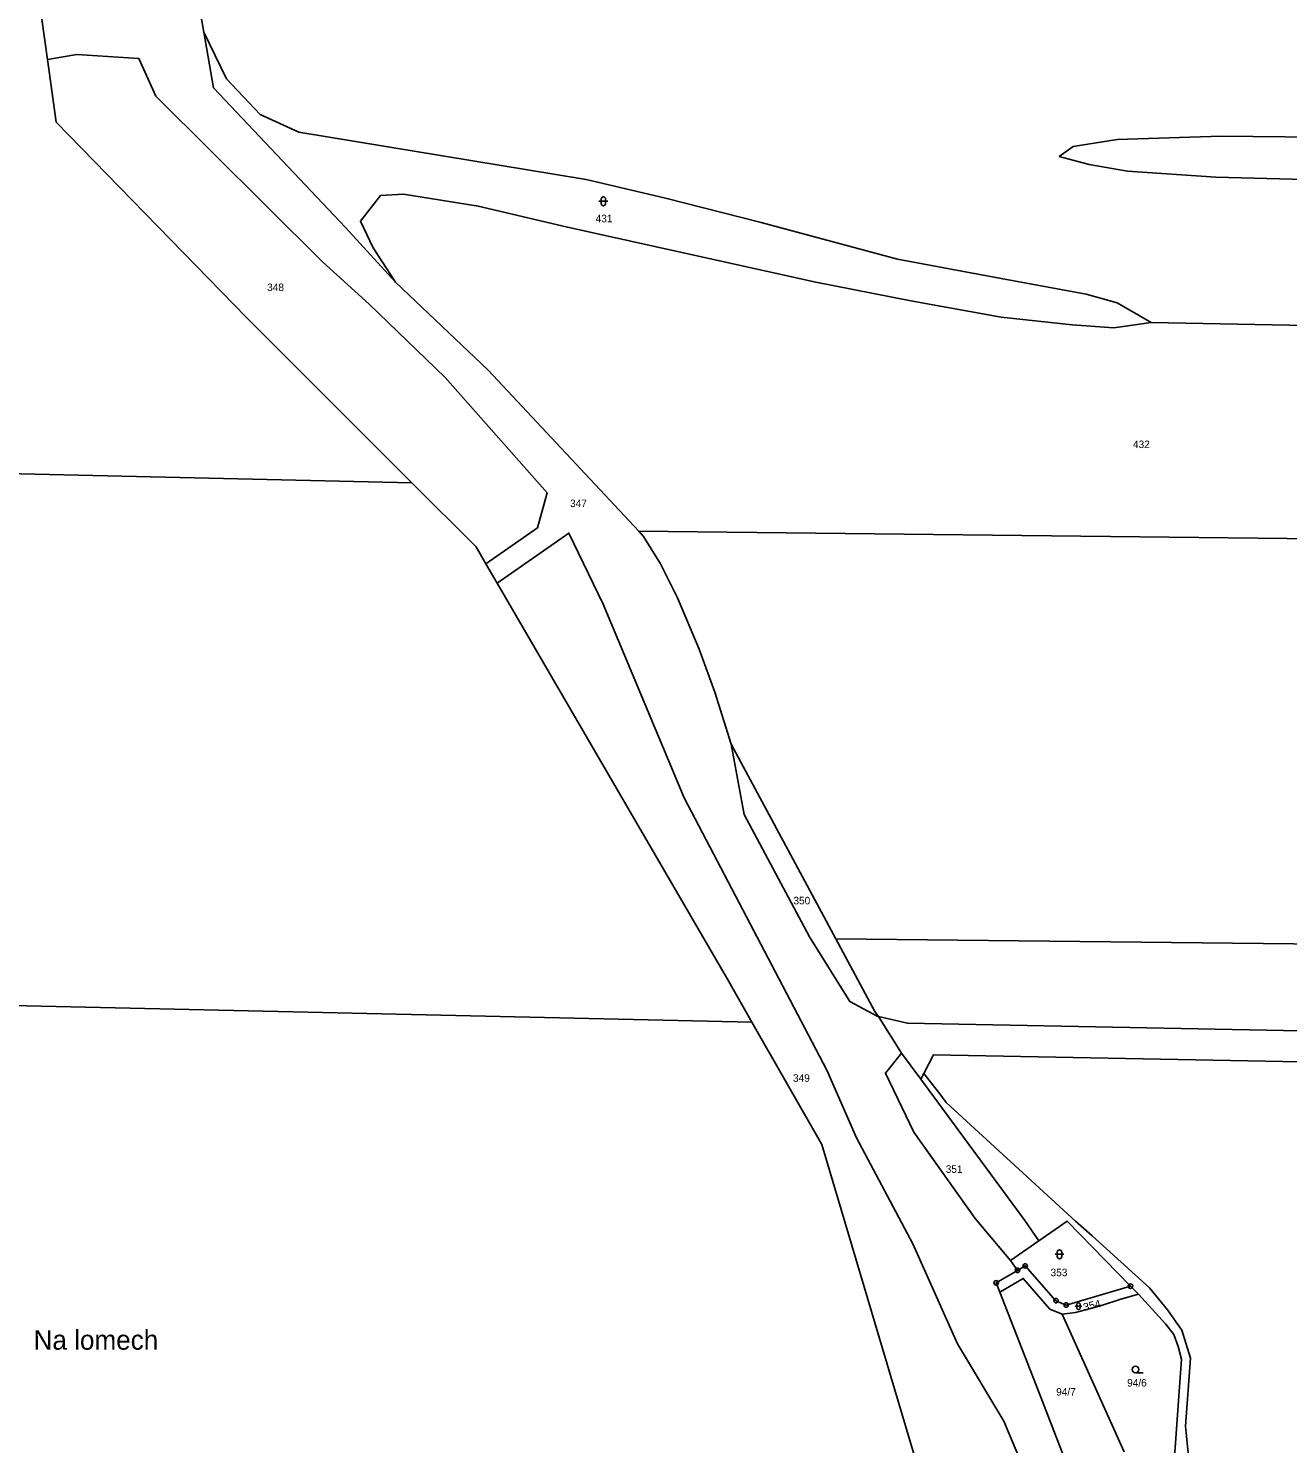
# Model space of a CAD drawing. Extents: x -769392 to -767038, y -1018329 to -1015269.
# Drawn here: x -768810.3 to -768526.3, y -1016085.5 to -1015766.2 of the extents above; entities that cross this region are included whole.
import ezdxf
from ezdxf.enums import TextEntityAlignment as Align

# ---------------------------------------------------------------- set-up
doc = ezdxf.new("R2010")
doc.units = 0
doc.header["$LTSCALE"] = 0.68
for name, color, linetype, lineweight in [('1', 7, 'Continuous', 25), ('3', 7, 'Continuous', 25), ('7', 7, 'Continuous', 13), ('8', 7, 'Continuous', 25)]:
    doc.layers.add(name, color=color, linetype=linetype, lineweight=lineweight)
doc.layers.add('2', color=7, linetype='Continuous')

msp = doc.modelspace()

# ---------------------------------------------------------------- linework, layer by layer
at = {"layer": '1'}
for p, q in [((-768770.74, -1015767.1), (-768772.34, -1015758.02)), ((-768806, -1015773.27), (-768807.26, -1015764.14)), ((-768707.1, -1015887.02), (-768704.55, -1015891.41)), ((-768628.22, -1015971.61), (-768651.76, -1015927.74)), ((-768647.11, -1015990.45), (-768839.41, -1015986.06)), ((-768613.34, -1015997.43), (-768618.56, -1015989.11)), ((-768613.34, -1015997.43), (-768609.02, -1016003.29)), ((-768609.02, -1016003.29), (-768608.35, -1016002)), ((-768582.41, -1016039.73), (-768588.81, -1016044.17)), ((-768587.21, -1016046.41), (-768588.81, -1016044.17)), ((-768561.73, -1016049.98), (-768559.94, -1016051.82)), ((-768563.14, -1016087.38), (-768577.15, -1016056.29))]:
    msp.add_line(p, q, dxfattribs=at)
for points in [[(-768557.04, -1015832.59), (-768564.72, -1015828.14), (-768571.74, -1015826.21), (-768590.86, -1015822.63), (-768614.27, -1015818.31), (-768645.03, -1015810.06), (-768666.63, -1015804.5), (-768684.47, -1015800.34), (-768749.33, -1015789.66), (-768758.05, -1015785.64), (-768765.64, -1015777.58), (-768770.74, -1015767.1)], [(-768770.74, -1015767.1), (-768768.54, -1015779.67), (-768738.76, -1015811.18), (-768727.48, -1015823.46)], [(-768707.1, -1015887.02), (-768695.45, -1015878.88), (-768693.27, -1015871), (-768716.28, -1015845), (-768733.46, -1015828.45), (-768743.96, -1015818.91), (-768781.53, -1015781.56), (-768785.37, -1015773.04), (-768799.39, -1015772.11), (-768806, -1015773.27)], [(-768806, -1015773.27), (-768804.05, -1015787.36), (-768761.11, -1015831.46), (-768723.8, -1015868.72)], [(-768727.48, -1015823.46), (-768732.57, -1015815.73), (-768735.41, -1015809.71), (-768730.9, -1015803.95), (-768725.67, -1015803.63), (-768708.82, -1015806.32), (-768688.73, -1015811.09), (-768632.66, -1015823.46), (-768611.29, -1015827.67), (-768590.89, -1015831.39), (-768574.88, -1015833.14), (-768565.46, -1015833.76), (-768557.04, -1015832.59)], [(-768672.64, -1015879.68), (-768706.61, -1015843.33), (-768727.48, -1015823.46)], [(-768393.76, -1015882.77), (-768393.24, -1015835.72), (-768557.04, -1015832.59)], [(-769059, -1015861.06), (-768887.32, -1015864.98), (-768723.8, -1015868.72)], [(-768723.8, -1015868.72), (-768709.33, -1015883.18), (-768707.1, -1015887.02)], [(-768393.76, -1015882.77), (-768526.38, -1015881.3), (-768672.64, -1015879.68)], [(-768651.76, -1015927.74), (-768655.45, -1015915.94), (-768659.03, -1015906.25), (-768663.92, -1015894.68), (-768667.76, -1015887.04), (-768671.56, -1015880.83), (-768672.64, -1015879.68)], [(-768577.92, -1016113.27), (-768585.77, -1016091.21), (-768590.28, -1016080.47), (-768600.78, -1016062.99), (-768610.85, -1016040.44), (-768623.52, -1016016.53), (-768630.25, -1016001.25), (-768662.38, -1015939.85), (-768680.7, -1015896.15), (-768688.37, -1015880.1), (-768704.55, -1015891.41)], [(-768704.55, -1015891.41), (-768652.35, -1015981.28), (-768647.11, -1015990.45)], [(-768618.56, -1015989.11), (-768618.84, -1015989.05), (-768625.01, -1015985.77), (-768634.09, -1015971.15), (-768648.87, -1015943.58), (-768651.76, -1015927.74)], [(-768618.56, -1015989.11), (-768619.4, -1015988.03), (-768628.22, -1015971.61)], [(-768628.22, -1015971.61), (-768504.28, -1015972.97), (-768394.77, -1015974.17)], [(-768647.11, -1015990.45), (-768631.35, -1016018.03), (-768596.9, -1016133.83)], [(-768395, -1015994.87), (-768504.06, -1015992.76), (-768612.03, -1015990.68), (-768618.56, -1015989.11)], [(-768588.81, -1016044.17), (-768596.74, -1016034.72), (-768610.57, -1016015.23), (-768616.99, -1016001.93), (-768613.34, -1015997.43)], [(-768608.35, -1016002), (-768606.17, -1015997.79), (-768503.74, -1015999.77), (-768400.14, -1016001.77), (-768395, -1015994.87)], [(-768582.41, -1016039.73), (-768585.54, -1016035.19), (-768609.02, -1016003.29)], [(-768531.03, -1016134.27), (-768536.67, -1016125.7), (-768546.18, -1016104.49), (-768548.19, -1016092.82), (-768549.32, -1016081.54), (-768548.21, -1016066.2), (-768550.18, -1016059.91), (-768553.38, -1016055.35), (-768557.44, -1016050.38), (-768570.36, -1016038.63), (-768574.11, -1016035.31), (-768603.29, -1016008.55), (-768604.7, -1016006.61), (-768608.35, -1016002)], [(-768582.41, -1016039.73), (-768576.01, -1016035.29), (-768561.73, -1016049.98)], [(-768587.21, -1016046.41), (-768585.49, -1016045.41), (-768578.53, -1016053.25), (-768576.22, -1016054.23), (-768561.73, -1016049.98)], [(-768587.21, -1016046.41), (-768592.03, -1016049.22), (-768591.21, -1016051.31)], [(-768577.15, -1016056.29), (-768579.88, -1016055.16), (-768585.91, -1016048.23), (-768591.21, -1016051.31)], [(-768575.9, -1016090.56), (-768582.47, -1016073.67), (-768591.21, -1016051.31)], [(-768568.47, -1016054.44), (-768563.87, -1016052.9), (-768559.94, -1016051.82)], [(-768559.94, -1016051.82), (-768553.83, -1016058.45), (-768551.98, -1016060.85), (-768550.95, -1016063.59), (-768550.23, -1016066.43), (-768551.76, -1016087.46), (-768550.46, -1016107.42), (-768550.51, -1016108.5)], [(-768568.47, -1016054.44), (-768574.14, -1016055.95), (-768577.15, -1016056.29)]]:
    msp.add_lwpolyline(points, dxfattribs=at)
msp.add_lwpolyline([(-768562.42, -1015798.46), (-768542.47, -1015799.78), (-768505.13, -1015800.77), (-768469.57, -1015803.07), (-768439.12, -1015804.99), (-768420.78, -1015807.18), (-768395.06, -1015808.66), (-768391.9, -1015808.02), (-768394.8, -1015806.1), (-768405.31, -1015801.53), (-768414.59, -1015798.93), (-768432.56, -1015794.35), (-768442.59, -1015793.04), (-768450.35, -1015792.69), (-768505.18, -1015790.92), (-768541.24, -1015790.54), (-768564.76, -1015791.31), (-768574.64, -1015792.9), (-768577.78, -1015795.16), (-768571.04, -1015796.95)], close=True, dxfattribs=at)
at = {"layer": '3'}
for p, q in [((-768681.611, -1015805.231), (-768679.609, -1015805.231)), ((-768681.111, -1015804.731), (-768681.111, -1015805.732)), ((-768680.109, -1015805.732), (-768680.109, -1015804.731)), ((-768578.231, -1016042.281), (-768578.231, -1016043.282)), ((-768577.229, -1016043.282), (-768577.229, -1016042.281)), ((-768578.731, -1016042.781), (-768576.729, -1016042.781)), ((-768574.231, -1016054.481), (-768572.669, -1016054.481)), ((-768573.84, -1016054.09), (-768573.84, -1016054.871)), ((-768573.06, -1016054.871), (-768573.06, -1016054.09)), ((-768560.583, -1016069.53), (-768558.833, -1016069.53))]:
    msp.add_line(p, q, dxfattribs=at)
msp.add_circle((-768560.5829, -1016068.7798), 0.75, dxfattribs=at)
for centre, radius, start, end in [((-768680.61, -1015804.7309), 0.5, 0, 180), ((-768680.61, -1015805.7309), 0.5, 180, 359.98789), ((-768577.73, -1016042.2809), 0.5, 0, 180), ((-768577.73, -1016043.2809), 0.5, 180, 359.98789), ((-768573.45, -1016054.0907), 0.39, 0, 180), ((-768573.45, -1016054.8707), 0.39, 180, 359.98789)]:
    msp.add_arc(centre, radius, start, end, dxfattribs=at)
at = {"layer": '8'}
for centre, radius in [((-768587.21, -1016046.4099), 0.5), ((-768585.49, -1016045.4099), 0.5), ((-768585.49, -1016045.4099), 0.0303), ((-768592.03, -1016049.2199), 0.5), ((-768587.21, -1016046.4099), 0.0303), ((-768592.03, -1016049.2199), 0.0303), ((-768561.73, -1016049.9799), 0.5), ((-768561.73, -1016049.9799), 0.0303), ((-768578.53, -1016053.2499), 0.5), ((-768578.53, -1016053.2499), 0.0303), ((-768576.22, -1016054.2299), 0.5), ((-768576.22, -1016054.2299), 0.0303)]:
    msp.add_circle(centre, radius, dxfattribs=at)

# ---------------------------------------------------------------- texts
at = {"layer": '2'}
for s, p in [('431', (-768682.36, -1015809.975)), ('348', (-768756.45, -1015825.495)), ('432', (-768561.16, -1015860.915)), ('347', (-768688.13, -1015874.235)), ('350', (-768637.75, -1015963.845)), ('349', (-768637.85, -1016003.875)), ('351', (-768603.4, -1016024.415)), ('353', (-768579.75, -1016047.735))]:
    msp.add_text(s, height=1.7, dxfattribs=at).set_placement(p)
at = {"layer": '2', "width": 1.05}
msp.add_text('354', height=1.7, rotation=14, dxfattribs=at).set_placement((-768572.157, -1016055.582))
at = {"layer": '2'}
for s, p in [('94/6', (-768560.269, -1016072.625)), ('94/7', (-768576.279, -1016074.655))]:
    msp.add_text(s, height=1.7, dxfattribs=at).set_placement(p, align=Align.CENTER)
at = {"layer": '7'}
msp.add_text('Na lomech', height=4.4, dxfattribs=at).set_placement((-768795.08, -1016064.31), align=Align.CENTER)

doc.saveas('drawing.dxf')
